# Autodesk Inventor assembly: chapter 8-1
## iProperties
Created: 2006-03
Part Number: chapter 8-1
Document SubType Name: Weldment
Designer: Elise Moss
Weld Material: Welded Aluminum-6061
Author: Elise Moss
